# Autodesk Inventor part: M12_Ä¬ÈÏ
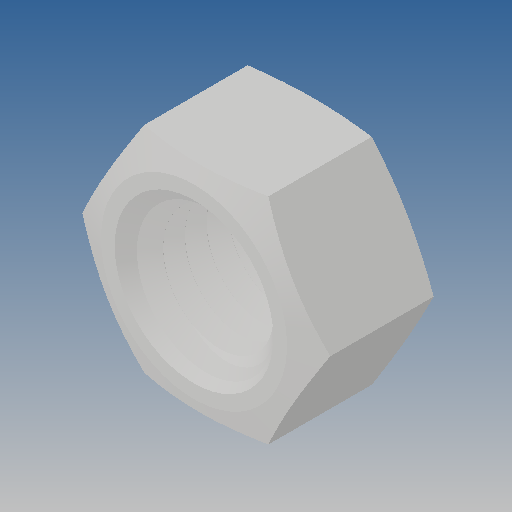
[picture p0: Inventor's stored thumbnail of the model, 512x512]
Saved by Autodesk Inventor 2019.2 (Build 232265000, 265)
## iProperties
Created: 2010-06
Part Number: M12_Ä¬ÈÏ
Material: Ogólny
Document SubType Name: Modeling
Designer: CADENGINEERING4
Density: 1 g/cm^3
Appearance: Domyślna
Author: CADENGINEERING4
Revision Number: ÈÎºÎ
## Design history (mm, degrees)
feature "NONE"
node "Bryła1"
